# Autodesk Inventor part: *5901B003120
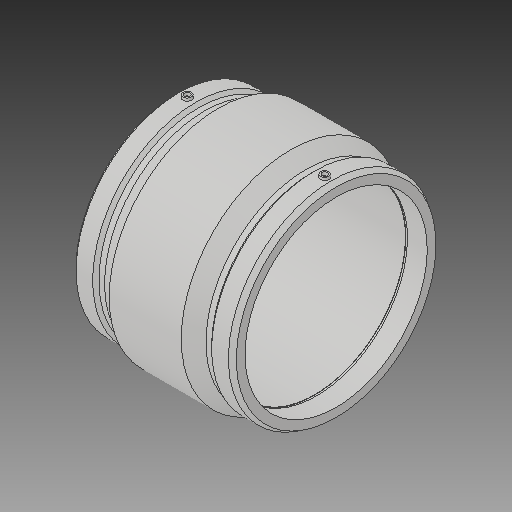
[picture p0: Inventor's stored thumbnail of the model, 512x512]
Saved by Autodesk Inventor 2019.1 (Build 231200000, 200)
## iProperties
Created: 2017-06
Part Number: *5901B003120
Material: Generic
Description: PLASSON IPS COUPLER 12''
Document SubType Name: Modeling
Designer: KIM
Mass: 8622.19 g
Surface Area: 6772.47 cm^2
Volume: 8622.19 cm^3
Density: 1 g/cm^3
Appearance: Default
Author: KIM
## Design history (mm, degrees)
derived "5901B.ipt"
feature "Solid1::5901B.ipt"
tag "TaggingFeature1"
body "Solid1"
other parameters: "d0" = 284.48, "d1" = 323.4, "d2" = 388.62, "d3" = 139.954, "d4" = 71.12, "d5" = 349.758, "d6" = 258.72, "d7" = 323.4, "d8" = 168 deg, "d10" = 55.9816, "d11" = 18.66053, "d13" = 284.48, "d14" = 17.6296, "d18" = 323.4, "d19" = 3.52592, "d20" = 168 deg, "d22" = 365.3028, "d23" = 388.62, "d24" = 354.34372, "d25" = 135 deg, "d26" = 128.016, "d27" = 135 deg, "d29" = 186.944, "d30" = 15, "d31" = 99.568, "d34" = 5 deg, "d35" = 15, "d39" = 5 deg, "d41" = 4, "d42" = 14, "d43" = 0, "d45" = 4, "d46" = 14, "d47" = 0, "d48" = 3, "d49" = 0, "d50" = 3, "d51" = 0, "d52" = 40.58666, "d53" = 10.14666, "d55" = 139.954, "d_" = 323.4, "L_" = 284.48, "L_1" = 139.954, "D_" = 388.62, "A_" = 186.944, "d_2" = 12, "B_" = 186.944
